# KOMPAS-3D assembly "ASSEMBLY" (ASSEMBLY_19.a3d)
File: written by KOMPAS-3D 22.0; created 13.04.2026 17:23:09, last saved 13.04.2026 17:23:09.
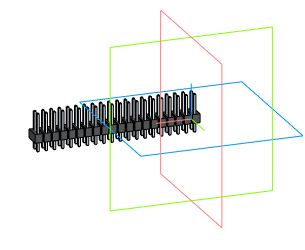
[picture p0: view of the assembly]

Document properties: Автор: Andrey; Полное имя файла: C:\Users\User1\Documents\ASSEMBLY_19.a3d

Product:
- Component [detail]: Body  | qty 1  | source file: Body_20.m3d
- Component [detail]: LeadsArray  | qty 1  | source file: LeadsArray.m3d
- Part/product: ASSEMBLY

Referenced files in C:\Users\User1\Documents\: Body_20.m3d, LeadsArray.m3d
